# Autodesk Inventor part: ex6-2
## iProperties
Author: Administrator
Created: 2001-09
Part Number: ex6-2
Document SubType Name: Modeling
Designer: Administrator
Control State: 0
Master: False
Checked Out: False
PropertySet Name: Design Tracking Control
Length Units: 11272
Angle Units: 11279
Time Units: 11290
Mass Units: 11286
Shininess: 3
Angle Display Precision: 2
Document Length Units: 11272
Document Angle Units: 11286
Document Time Units: 11279
Document Mass Units: 11290
Document Length Units Precision: 3
Document Angle Units Precision: 2
Compacted: False
PropertySet Name: _Private Model Information
Density: 0.0
Volumn: 0.0
Area: 0.0
PropertySet Name: Model Information
